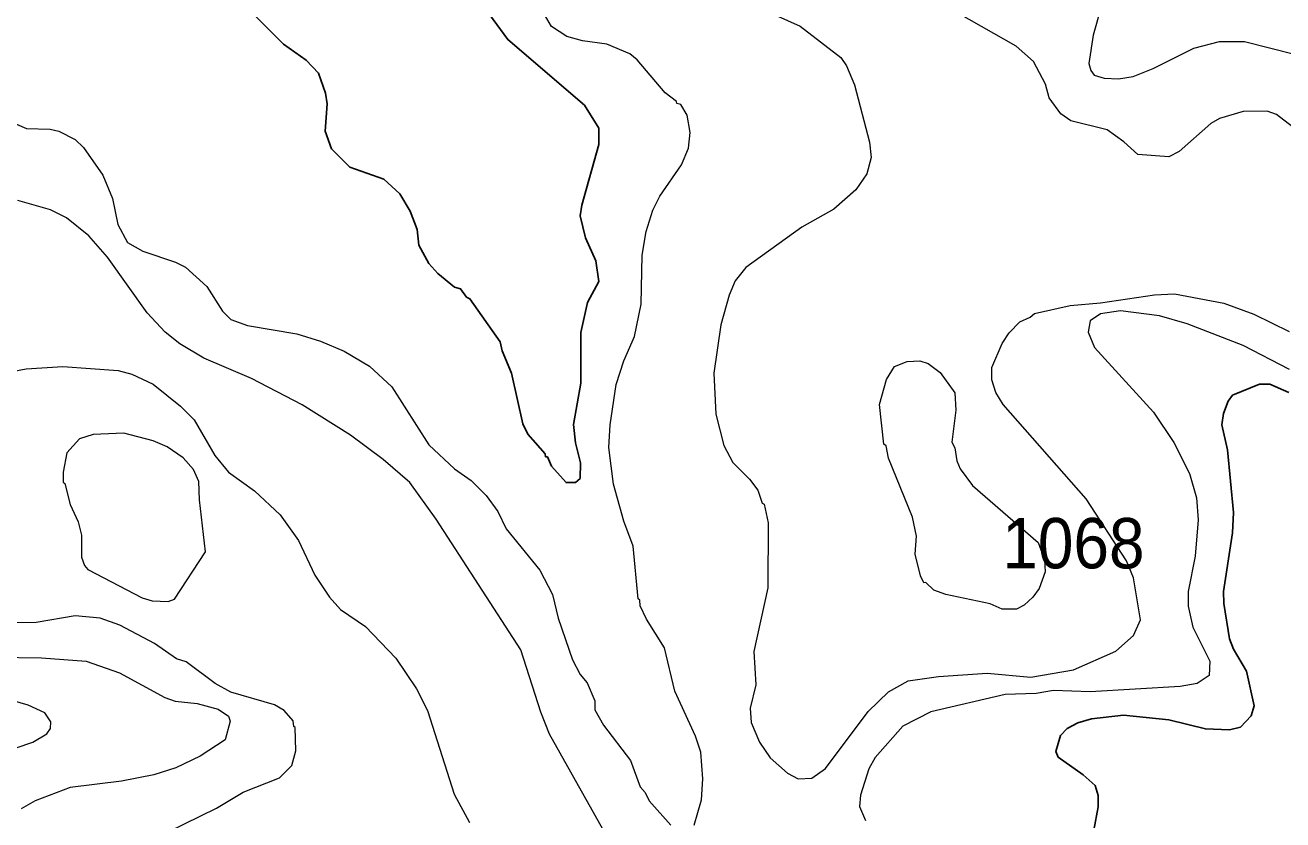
# Model space of a CAD drawing. Extents: x 447.8 to 473.9, y 7733.1 to 7760.8.
# Drawn here: x 464.533 to 466.532, y 7753.726 to 7754.988 of the extents above; entities that cross this region are included whole.
import ezdxf

# ---------------------------------------------------------------- set-up
doc = ezdxf.new("R2010")
doc.units = 0
doc.header["$LTSCALE"] = 0.032
doc.layers.add('1', color=7, linetype='Continuous', lineweight=25)
doc.layers.add('2', color=7, linetype='Continuous', lineweight=13)
doc.layers.add('21', color=7, linetype='Continuous')

msp = doc.modelspace()

# ---------------------------------------------------------------- linework, layer by layer
at = {"layer": '1'}
for points in [[(464.8568, 7755.0456), (464.9436, 7754.9579), (464.9797, 7754.9324), (464.9992, 7754.9117), (465.0103, 7754.88), (465.0126, 7754.8629), (465.0095, 7754.8195), (465.0195, 7754.7913), (465.0489, 7754.7624), (465.1029, 7754.7433), (465.1285, 7754.7203), (465.1449, 7754.6924), (465.156, 7754.6636), (465.1585, 7754.6386), (465.1746, 7754.6096), (465.189, 7754.5933), (465.2153, 7754.572), (465.2248, 7754.5692), (465.2343, 7754.5562), (465.2398, 7754.5535), (465.288, 7754.4849), (465.2908, 7754.4708), (465.3057, 7754.4354), (465.3237, 7754.3545), (465.3318, 7754.3382), (465.3591, 7754.307), (465.3599, 7754.3025), (465.3629, 7754.3021), (465.3692, 7754.2875), (465.3925, 7754.2615), (465.4076, 7754.2618), (465.4148, 7754.268), (465.4157, 7754.2927), (465.4076, 7754.3248), (465.4046, 7754.3538), (465.4158, 7754.4194), (465.4158, 7754.5), (465.4268, 7754.5477), (465.4445, 7754.5806), (465.4399, 7754.6139), (465.4236, 7754.6502), (465.4151, 7754.6851), (465.4174, 7754.702), (465.4446, 7754.7986), (465.4444, 7754.8245), (465.4216, 7754.8609), (465.2998, 7754.9651), (465.2708, 7755.005)], [(466.2144, 7753.7971), (466.1745, 7753.8252), (466.171, 7753.8344), (466.1782, 7753.8599), (466.1891, 7753.8709), (466.2061, 7753.8799), (466.2275, 7753.8864), (466.2782, 7753.8919), (466.3504, 7753.8847), (466.4085, 7753.8703), (466.447, 7753.8688), (466.4646, 7753.8731), (466.4811, 7753.8912), (466.486, 7753.907), (466.4738, 7753.9617), (466.4532, 7753.9967), (466.4471, 7754.0132), (466.4378, 7754.0695), (466.4371, 7754.0887), (466.4515, 7754.1817), (466.4531, 7754.2138), (466.4438, 7754.3135), (466.4347, 7754.3533), (466.4373, 7754.3713), (466.4449, 7754.391), (466.4517, 7754.4002), (466.4944, 7754.4179), (466.5112, 7754.4178), (466.5414, 7754.4047)], [(466.2067, 7753.6801), (466.2313, 7753.7094), (466.2382, 7753.7466), (466.2382, 7753.7645), (466.2335, 7753.7801), (466.2144, 7753.7971)]]:
    msp.add_lwpolyline(points, dxfattribs=at)
at = {"layer": '2'}
for points in [[(466.5471, 7754.8264), (466.5215, 7754.8459), (466.5068, 7754.8515), (466.4687, 7754.8506), (466.4309, 7754.8396), (466.4171, 7754.8317), (466.3667, 7754.7872), (466.3507, 7754.7787), (466.3014, 7754.7823), (466.2789, 7754.8027), (466.2522, 7754.8216), (466.1945, 7754.8362), (466.1787, 7754.847), (466.1604, 7754.8727), (466.1544, 7754.8944), (466.1356, 7754.93), (466.1078, 7754.9546), (465.9227, 7755.06)], [(465.6886, 7755.0205), (465.7647, 7754.9865)], [(466.2422, 7755.0147), (466.2303, 7754.972), (466.2231, 7754.9272), (466.2263, 7754.9157), (466.2319, 7754.9084), (466.2475, 7754.9036)], [(465.5097, 7754.0747), (465.5072, 7754.0767), (465.4991, 7754.1605), (465.4844, 7754.2002), (465.4681, 7754.2589), (465.4606, 7754.3173), (465.4624, 7754.3533), (465.472, 7754.4174), (465.4845, 7754.4548), (465.5014, 7754.4936), (465.5119, 7754.5449), (465.5137, 7754.6229), (465.5199, 7754.66), (465.5303, 7754.694), (465.5413, 7754.7162), (465.5758, 7754.7663), (465.5869, 7754.7925), (465.5898, 7754.8176), (465.5849, 7754.8448), (465.5748, 7754.8622), (465.5685, 7754.8636), (465.568, 7754.8667), (465.5502, 7754.8806), (465.5057, 7754.933), (465.4938, 7754.9426), (465.4574, 7754.958), (465.4187, 7754.9629), (465.394, 7754.9699), (465.3692, 7754.9857), (465.3583, 7755.005)], [(465.7647, 7754.9865), (465.8293, 7754.9365), (465.8381, 7754.9231), (465.851, 7754.8931), (465.8745, 7754.8021), (465.8775, 7754.7777)], [(466.2475, 7754.9036), (466.2707, 7754.9028), (466.2938, 7754.9063), (466.3258, 7754.9193), (466.3902, 7754.9515), (466.4309, 7754.9621), (466.4706, 7754.962), (466.5504, 7754.9419)], [(464.4712, 7754.8515), (464.5349, 7754.8236), (464.5729, 7754.8227), (464.5866, 7754.8195), (464.6125, 7754.8066), (464.6257, 7754.7935), (464.6563, 7754.7498), (464.6717, 7754.7127), (464.6803, 7754.6711), (464.6954, 7754.6429), (464.7197, 7754.6288), (464.7716, 7754.6117), (464.7875, 7754.6036), (464.8216, 7754.5728), (464.8466, 7754.5335), (464.8596, 7754.5207), (464.8864, 7754.5109), (464.9649, 7754.4976), (465.0025, 7754.4858), (465.04, 7754.4702), (465.0802, 7754.4466), (465.1158, 7754.4133), (465.1746, 7754.3213), (465.2151, 7754.2833), (465.2416, 7754.265), (465.2657, 7754.2409), (465.2839, 7754.2157), (465.2971, 7754.1882), (465.3506, 7754.1223), (465.3708, 7754.0838), (465.3802, 7754.0462), (465.4026, 7753.9797), (465.4151, 7753.9564), (465.426, 7753.9436), (465.4381, 7753.9146), (465.4383, 7753.9003), (465.4522, 7753.8761), (465.4947, 7753.82), (465.5104, 7753.7784), (465.5185, 7753.769), (465.5245, 7753.7559), (465.5591, 7753.7174)], [(465.8775, 7754.7777), (465.8703, 7754.752), (465.8532, 7754.7262), (465.8182, 7754.6959), (465.7672, 7754.6673), (465.6782, 7754.6031), (465.6612, 7754.582), (465.6515, 7754.5593), (465.6387, 7754.512), (465.6275, 7754.435), (465.6307, 7754.3702), (465.6431, 7754.3204), (465.6573, 7754.2933), (465.6843, 7754.2671), (465.6975, 7754.2493), (465.7043, 7754.229), (465.7075, 7754.2272), (465.7139, 7754.1973), (465.7131, 7754.0944), (465.6909, 7753.9933), (465.6939, 7753.9402), (465.6852, 7753.9031), (465.6868, 7753.8805), (465.6999, 7753.8489), (465.717, 7753.8241), (465.7447, 7753.7997), (465.7615, 7753.7908), (465.7829, 7753.7918), (465.8046, 7753.8072), (465.8728, 7753.8977), (465.905, 7753.929), (465.9362, 7753.9468), (465.9842, 7753.9537), (466.0615, 7753.9585), (466.1311, 7753.9522)], [(464.8928, 7754.4268), (464.8167, 7754.4589), (464.7789, 7754.482), (464.7556, 7754.5001), (464.727, 7754.5311), (464.6637, 7754.6193), (464.634, 7754.6536), (464.5986, 7754.6817), (464.5734, 7754.6946), (464.5212, 7754.7096)], [(466.1311, 7753.9522), (466.1991, 7753.9639), (466.266, 7753.9939), (466.2943, 7754.0187), (466.3054, 7754.0434), (466.2941, 7754.1099), (466.2834, 7754.1374), (466.2192, 7754.2359), (466.0873, 7754.3852), (466.0753, 7754.4047), (466.0691, 7754.4247), (466.0691, 7754.4442), (466.0858, 7754.4825), (466.0969, 7754.4993), (466.1134, 7754.5167), (466.1301, 7754.5241), (466.137, 7754.5301), (466.1937, 7754.5429), (466.2421, 7754.5469), (466.3277, 7754.5597), (466.3592, 7754.5614), (466.4381, 7754.5465), (466.4854, 7754.5291), (466.5418, 7754.5015)], [(466.5424, 7754.4408), (466.4684, 7754.479), (466.3798, 7754.5136), (466.3357, 7754.5261), (466.2735, 7754.534), (466.2421, 7754.5294), (466.2255, 7754.5186), (466.2223, 7754.5004), (466.2323, 7754.4761), (466.3261, 7754.3731), (466.3586, 7754.3251), (466.3833, 7754.2759), (466.3946, 7754.2371), (466.397, 7754.2023), (466.3921, 7754.1445), (466.381, 7754.0883), (466.381, 7754.0652), (466.3884, 7754.0316), (466.4155, 7753.978), (466.4144, 7753.9551), (466.3955, 7753.9424), (466.3687, 7753.9377), (466.2257, 7753.9289), (466.167, 7753.9312), (466.1395, 7753.9265), (466.0904, 7753.9248), (465.9721, 7753.8975), (465.9277, 7753.8746), (465.8839, 7753.8248), (465.8738, 7753.8069), (465.8604, 7753.7651), (465.8591, 7753.7469), (465.8683, 7753.725)], [(464.5039, 7754.4364), (464.5344, 7754.4419), (464.5928, 7754.4459), (464.6806, 7754.4393), (464.7027, 7754.4337), (464.7363, 7754.4176), (464.7799, 7754.3827), (464.8015, 7754.3612), (464.8342, 7754.3045), (464.8559, 7754.2781), (464.8974, 7754.2484), (464.938, 7754.2102), (464.9673, 7754.1695), (464.9932, 7754.1143), (465.0166, 7754.0794), (465.034, 7754.0598), (465.0738, 7754.0328), (465.1222, 7753.9828), (465.1548, 7753.9338), (465.1725, 7753.8997), (465.2145, 7753.7664), (465.2388, 7753.7217)], [(465.1862, 7754.2031), (465.144, 7754.2615), (465.1018, 7754.2981), (465.0497, 7754.3366), (464.973, 7754.3851), (464.8928, 7754.4268)], [(465.4557, 7753.7023), (465.3663, 7753.8621), (465.3522, 7753.8968), (465.3205, 7753.9958), (465.1862, 7754.2031)], [(465.598, 7753.8585), (465.5655, 7753.9303), (465.5488, 7753.999), (465.5204, 7754.0444), (465.5104, 7754.0655), (465.5097, 7754.0747)], [(464.8598, 7753.9287), (464.8349, 7753.9421), (464.7888, 7753.9768), (464.7735, 7753.9813), (464.7384, 7754.0058), (464.6836, 7754.0348), (464.6522, 7754.0463), (464.6123, 7754.0498), (464.5506, 7754.039), (464.4996, 7754.0386)], [(464.4856, 7753.9842), (464.5589, 7753.9833), (464.6299, 7753.9778), (464.6828, 7753.9595), (464.7551, 7753.9203), (464.7714, 7753.9145), (464.8063, 7753.9105), (464.8395, 7753.9015), (464.8562, 7753.8903), (464.8586, 7753.8827), (464.8509, 7753.8529), (464.8108, 7753.8267), (464.7726, 7753.8085), (464.7373, 7753.7972), (464.686, 7753.7874), (464.6043, 7753.7772), (464.5488, 7753.7559), (464.5266, 7753.7432)], [(464.4936, 7753.8318), (464.5449, 7753.8494), (464.5671, 7753.8626), (464.5731, 7753.8709), (464.5739, 7753.8817), (464.5642, 7753.896), (464.5375, 7753.9079), (464.5123, 7753.9151)], [(464.9621, 7753.8724), (464.9597, 7753.8739), (464.9588, 7753.883), (464.9444, 7753.8992), (464.9293, 7753.9087), (464.8598, 7753.9287)], [(464.5267, 7753.5642), (464.5507, 7753.5935), (464.5888, 7753.6108), (464.6325, 7753.6453), (464.6901, 7753.6726), (464.7147, 7753.6885), (464.7601, 7753.7068), (464.8372, 7753.7441), (464.8794, 7753.7697), (464.937, 7753.7924), (464.9565, 7753.8121), (464.9631, 7753.8352), (464.9621, 7753.8724)], [(465.5959, 7753.7175), (465.6075, 7753.7577), (465.6098, 7753.7908), (465.6065, 7753.8334), (465.598, 7753.8585)]]:
    msp.add_lwpolyline(points, dxfattribs=at)
for points in [[(465.9048, 7754.3003), (465.9014, 7754.3199), (465.8973, 7754.3226), (465.8904, 7754.3852), (465.9016, 7754.425), (465.9144, 7754.4458), (465.9348, 7754.4538), (465.9547, 7754.4546), (465.9681, 7754.4508), (465.9871, 7754.4364), (466.0105, 7754.4039), (466.0121, 7754.3763), (466.0058, 7754.3257), (466.0105, 7754.3168), (466.0136, 7754.2958), (466.019, 7754.2832), (466.0384, 7754.257), (466.1426, 7754.1665), (466.1529, 7754.1389), (466.1537, 7754.1199), (466.1445, 7754.0933), (466.1344, 7754.0792), (466.1207, 7754.067), (466.1086, 7754.0605), (466.0854, 7754.0602), (466.0666, 7754.0691), (465.9959, 7754.0835), (465.977, 7754.0908), (465.9641, 7754.1025), (465.9611, 7754.1022), (465.9558, 7754.1133), (465.9473, 7754.1476), (465.9496, 7754.1762), (465.9429, 7754.2067)], [(464.8194, 7754.1513), (464.8099, 7754.2339), (464.809, 7754.2631), (464.8003, 7754.282), (464.7842, 7754.3007), (464.7585, 7754.3184), (464.7363, 7754.3279), (464.6899, 7754.34), (464.6411, 7754.3376), (464.6191, 7754.3311), (464.5992, 7754.3086), (464.5934, 7754.2779), (464.5934, 7754.2619), (464.5959, 7754.26), (464.6042, 7754.2268), (464.6174, 7754.1991), (464.6222, 7754.1781), (464.6223, 7754.1432), (464.627, 7754.1296), (464.6324, 7754.1235), (464.719, 7754.0782), (464.7346, 7754.0736), (464.7601, 7754.0724), (464.7703, 7754.0765)]]:
    msp.add_lwpolyline(points, close=True, dxfattribs=at)

# ---------------------------------------------------------------- texts
at = {"layer": '21', "width": 0.95}
msp.add_text('1068', height=0.08, dxfattribs=at).set_placement((466.0858, 7754.1252))

doc.saveas('drawing.dxf')
